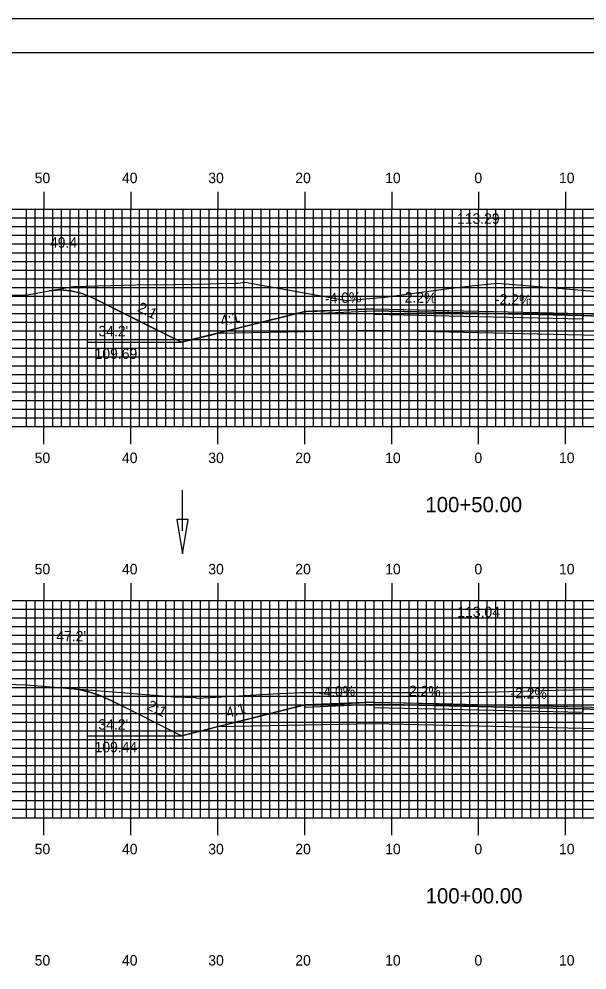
# Model space of a CAD drawing. Extents: x 1766513 to 1766856, y 442591 to 442811.
# Drawn here: x 1766626 to 1766691.4, y 442701.2 to 442810.5 of the extents above; entities that cross this region are included whole.
import ezdxf

# ---------------------------------------------------------------- set-up
doc = ezdxf.new("R2010")
doc.units = 0
for name, color, linetype in [('ANNOTATION', 7, 'Continuous'), ('BORDER', 7, 'Continuous'), ('D_Drainage_Ditch_Line', 7, 'Continuous'), ('D_Roadway_Centerline', 7, 'Continuous'), ('D_Roadway_Centerline_Text', 7, 'Continuous'), ('D_Roadway_Edge_Shoulder', 7, 'Continuous'), ('D_Roadway_Edge_TW', 7, 'Continuous'), ('D_Roadway_Pavement', 7, 'Continuous'), ('D_Roadway_SlopeLines', 7, 'Continuous'), ('D_Roadway_SubGrade', 7, 'Continuous'), ('D_Text_Standard', 7, 'Continuous'), ('H_V ANNOTATION', 7, 'Continuous'), ('MAJOR', 7, 'Continuous'), ('MINOR', 7, 'Continuous'), ('PDRAIN', 7, 'Continuous'), ('PLOT BOUNDARY', 7, 'Continuous'), ('S_Roadway_Centerline', 7, 'Continuous')]:
    doc.layers.add(name, color=color, linetype=linetype)

msp = doc.modelspace()

# ---------------------------------------------------------------- linework, layer by layer
at = {"layer": 'BORDER'}
msp.add_lwpolyline([(1766529.31, 442596.67), (1766849.31, 442596.67), (1766849.31, 442806.67), (1766529.31, 442806.67)], close=True, dxfattribs=at)
at = {"layer": 'D_Drainage_Ditch_Line'}
msp.add_line((1766644.85, 442751.66), (1766644.85, 442756.36), dxfattribs=at)
msp.add_lwpolyline([(1766645.5, 442752.97), (1766644.19, 442752.97), (1766644.85, 442749.03)], close=True, dxfattribs=at)
at = {"layer": 'D_Roadway_Centerline'}
for points in [[(1766629.51, 442779.27), (1766630.76, 442779.39), (1766631.63, 442779.32), (1766632.01, 442779.29), (1766633.03, 442779.04), (1766633.26, 442778.99), (1766634.51, 442778.47), (1766638.94, 442776.25), (1766644.74, 442773.36), (1766648.51, 442774.3), (1766648.74, 442774.36), (1766658.91, 442776.9), (1766660.34, 442776.96), (1766666.91, 442777.22), (1766675.35, 442777.03), (1766678.91, 442776.96), (1766690.91, 442776.69), (1766698.91, 442776.37)], [(1766631.7, 442733.58), (1766632.95, 442733.41), (1766634.2, 442733.11), (1766635.45, 442732.69), (1766636.7, 442732.13), (1766639.51, 442730.72), (1766644.74, 442728.11), (1766648.06, 442728.94), (1766648.74, 442729.11), (1766650.05, 442729.44), (1766658.91, 442731.65), (1766658.91, 442731.65), (1766663.43, 442731.83), (1766666.91, 442731.97), (1766674.35, 442731.81), (1766678.91, 442731.71), (1766690.91, 442731.44), (1766697.03, 442731.2)]]:
    msp.add_lwpolyline(points, dxfattribs=at)
at = {"layer": 'D_Roadway_Edge_Shoulder'}
for points in [[(1766666.91, 442777.22), (1766658.91, 442776.9), (1766658.91, 442776.65), (1766666.91, 442776.97)], [(1766690.91, 442776.69), (1766698.91, 442776.37), (1766698.91, 442776.12), (1766690.91, 442776.44)], [(1766666.91, 442731.97), (1766658.91, 442731.65), (1766658.91, 442731.4), (1766666.91, 442731.72)], [(1766690.91, 442731.44), (1766698.91, 442731.12), (1766698.91, 442730.87), (1766690.91, 442731.19)]]:
    msp.add_lwpolyline(points, close=True, dxfattribs=at)
at = {"layer": 'D_Roadway_Edge_TW'}
for points in [[(1766666.91, 442776.97), (1766666.91, 442777.22), (1766678.91, 442776.96), (1766690.91, 442776.69), (1766690.91, 442776.44), (1766678.91, 442776.71)], [(1766666.91, 442731.72), (1766666.91, 442731.97), (1766678.91, 442731.71), (1766690.91, 442731.44), (1766690.91, 442731.19), (1766678.91, 442731.46)]]:
    msp.add_lwpolyline(points, close=True, dxfattribs=at)
at = {"layer": 'D_Roadway_Pavement'}
for points in [[(1766666.91, 442776.55), (1766666.91, 442776.97), (1766678.91, 442776.71), (1766690.91, 442776.44), (1766690.91, 442776.03), (1766678.91, 442776.29)], [(1766666.91, 442731.3), (1766666.91, 442731.72), (1766678.91, 442731.46), (1766690.91, 442731.19), (1766690.91, 442730.78), (1766678.91, 442731.04)]]:
    msp.add_lwpolyline(points, close=True, dxfattribs=at)
at = {"layer": 'D_Roadway_SlopeLines'}
for points in [[(1766644.74, 442773.36), (1766634.51, 442778.47), (1766633.26, 442778.99), (1766632.01, 442779.29), (1766630.76, 442779.39), (1766629.51, 442779.27)], [(1766658.91, 442776.9), (1766644.74, 442773.36)], [(1766644.74, 442728.11), (1766636.7, 442732.13), (1766635.45, 442732.69), (1766634.2, 442733.11), (1766632.95, 442733.41), (1766631.7, 442733.58)], [(1766658.91, 442731.65), (1766644.74, 442728.11)]]:
    msp.add_lwpolyline(points, dxfattribs=at)
at = {"layer": 'D_Roadway_SubGrade'}
for points in [[(1766666.91, 442774.72), (1766648.74, 442774.36), (1766658.91, 442776.9), (1766658.91, 442776.65), (1766666.91, 442776.97), (1766678.91, 442776.71), (1766690.91, 442776.44), (1766698.91, 442776.12), (1766698.91, 442776.37), (1766709.08, 442773.83), (1766690.91, 442774.19), (1766678.91, 442774.46)], [(1766666.91, 442729.47), (1766648.74, 442729.11), (1766658.91, 442731.65), (1766658.91, 442731.4), (1766666.91, 442731.72), (1766678.91, 442731.46), (1766690.91, 442731.19), (1766698.91, 442730.87), (1766698.91, 442731.12), (1766709.08, 442728.58), (1766690.91, 442728.94), (1766678.91, 442729.21)]]:
    msp.add_lwpolyline(points, close=True, dxfattribs=at)
at = {"layer": 'MAJOR'}
for p, q in [((1766628.91, 442790.67), (1766628.91, 442788.67)), ((1766638.91, 442790.67), (1766638.91, 442788.67)), ((1766648.91, 442790.67), (1766648.91, 442788.67)), ((1766658.91, 442790.67), (1766658.91, 442788.67)), ((1766668.91, 442790.67), (1766668.91, 442788.67)), ((1766678.91, 442790.67), (1766678.91, 442788.67)), ((1766688.91, 442790.67), (1766688.91, 442788.67)), ((1766538.91, 442788.67), (1766818.91, 442788.67)), ((1766538.91, 442788.67), (1766818.91, 442788.67)), ((1766628.91, 442763.67), (1766628.91, 442788.67)), ((1766638.91, 442763.67), (1766638.91, 442788.67)), ((1766648.91, 442763.67), (1766648.91, 442788.67)), ((1766658.91, 442763.67), (1766658.91, 442788.67)), ((1766668.91, 442763.67), (1766668.91, 442788.67)), ((1766678.91, 442763.67), (1766678.91, 442788.67)), ((1766688.91, 442763.67), (1766688.91, 442788.67)), ((1766538.91, 442783.67), (1766818.91, 442783.67)), ((1766538.91, 442778.67), (1766818.91, 442778.67)), ((1766538.91, 442773.67), (1766818.91, 442773.67)), ((1766538.91, 442768.67), (1766818.91, 442768.67)), ((1766538.91, 442763.67), (1766818.91, 442763.67)), ((1766538.91, 442763.67), (1766818.91, 442763.67)), ((1766628.91, 442761.66), (1766628.91, 442763.67)), ((1766638.91, 442761.66), (1766638.91, 442763.67)), ((1766648.91, 442761.66), (1766648.91, 442763.67)), ((1766658.91, 442761.66), (1766658.91, 442763.67)), ((1766668.91, 442761.66), (1766668.91, 442763.67)), ((1766678.91, 442761.66), (1766678.91, 442763.67)), ((1766688.91, 442761.66), (1766688.91, 442763.67)), ((1766628.91, 442745.67), (1766628.91, 442743.67)), ((1766638.91, 442745.67), (1766638.91, 442743.67)), ((1766648.91, 442745.67), (1766648.91, 442743.67)), ((1766658.91, 442745.67), (1766658.91, 442743.67)), ((1766668.91, 442745.67), (1766668.91, 442743.67)), ((1766678.91, 442745.67), (1766678.91, 442743.67)), ((1766688.91, 442745.67), (1766688.91, 442743.67)), ((1766538.91, 442743.67), (1766818.91, 442743.67)), ((1766538.91, 442743.67), (1766818.91, 442743.67)), ((1766628.91, 442718.67), (1766628.91, 442743.67)), ((1766638.91, 442718.67), (1766638.91, 442743.67)), ((1766648.91, 442718.67), (1766648.91, 442743.67)), ((1766658.91, 442718.67), (1766658.91, 442743.67)), ((1766668.91, 442718.67), (1766668.91, 442743.67)), ((1766678.91, 442718.67), (1766678.91, 442743.67)), ((1766688.91, 442718.67), (1766688.91, 442743.67)), ((1766538.91, 442738.67), (1766818.91, 442738.67)), ((1766538.91, 442733.67), (1766818.91, 442733.67)), ((1766538.91, 442728.67), (1766818.91, 442728.67)), ((1766538.91, 442723.67), (1766818.91, 442723.67)), ((1766538.91, 442718.67), (1766818.91, 442718.67)), ((1766538.91, 442718.67), (1766818.91, 442718.67)), ((1766628.91, 442716.66), (1766628.91, 442718.67)), ((1766638.91, 442716.66), (1766638.91, 442718.67)), ((1766648.91, 442716.66), (1766648.91, 442718.67)), ((1766658.91, 442716.66), (1766658.91, 442718.67)), ((1766668.91, 442716.66), (1766668.91, 442718.67)), ((1766678.91, 442716.66), (1766678.91, 442718.67)), ((1766688.91, 442716.66), (1766688.91, 442718.67))]:
    msp.add_line(p, q, dxfattribs=at)
at = {"layer": 'MINOR'}
for p, q in [((1766626.91, 442763.67), (1766626.91, 442788.67)), ((1766627.91, 442763.67), (1766627.91, 442788.67)), ((1766629.91, 442763.67), (1766629.91, 442788.67)), ((1766630.91, 442763.67), (1766630.91, 442788.67)), ((1766631.91, 442763.67), (1766631.91, 442788.67)), ((1766632.91, 442763.67), (1766632.91, 442788.67)), ((1766633.91, 442763.67), (1766633.91, 442788.67)), ((1766634.91, 442763.67), (1766634.91, 442788.67)), ((1766635.91, 442763.67), (1766635.91, 442788.67)), ((1766636.91, 442763.67), (1766636.91, 442788.67)), ((1766637.91, 442763.67), (1766637.91, 442788.67)), ((1766639.91, 442763.67), (1766639.91, 442788.67)), ((1766640.91, 442763.67), (1766640.91, 442788.67)), ((1766641.91, 442763.67), (1766641.91, 442788.67)), ((1766642.91, 442763.67), (1766642.91, 442788.67)), ((1766643.91, 442763.67), (1766643.91, 442788.67)), ((1766644.91, 442763.67), (1766644.91, 442788.67)), ((1766645.91, 442763.67), (1766645.91, 442788.67)), ((1766646.91, 442763.67), (1766646.91, 442788.67)), ((1766647.91, 442763.67), (1766647.91, 442788.67)), ((1766649.91, 442763.67), (1766649.91, 442788.67)), ((1766650.91, 442763.67), (1766650.91, 442788.67)), ((1766651.91, 442763.67), (1766651.91, 442788.67)), ((1766652.91, 442763.67), (1766652.91, 442788.67)), ((1766653.91, 442763.67), (1766653.91, 442788.67)), ((1766654.91, 442763.67), (1766654.91, 442788.67)), ((1766655.91, 442763.67), (1766655.91, 442788.67)), ((1766656.91, 442763.67), (1766656.91, 442788.67)), ((1766657.91, 442763.67), (1766657.91, 442788.67)), ((1766659.91, 442763.67), (1766659.91, 442788.67)), ((1766660.91, 442763.67), (1766660.91, 442788.67)), ((1766661.91, 442763.67), (1766661.91, 442788.67)), ((1766662.91, 442763.67), (1766662.91, 442788.67)), ((1766663.91, 442763.67), (1766663.91, 442788.67)), ((1766664.91, 442763.67), (1766664.91, 442788.67)), ((1766665.91, 442763.67), (1766665.91, 442788.67)), ((1766666.91, 442763.67), (1766666.91, 442788.67)), ((1766667.91, 442763.67), (1766667.91, 442788.67)), ((1766669.91, 442763.67), (1766669.91, 442788.67)), ((1766670.91, 442763.67), (1766670.91, 442788.67)), ((1766671.91, 442763.67), (1766671.91, 442788.67)), ((1766672.91, 442763.67), (1766672.91, 442788.67)), ((1766673.91, 442763.67), (1766673.91, 442788.67)), ((1766674.91, 442763.67), (1766674.91, 442788.67)), ((1766675.91, 442763.67), (1766675.91, 442788.67)), ((1766676.91, 442763.67), (1766676.91, 442788.67)), ((1766677.91, 442763.67), (1766677.91, 442788.67)), ((1766679.91, 442763.67), (1766679.91, 442788.67)), ((1766680.91, 442763.67), (1766680.91, 442788.67)), ((1766681.91, 442763.67), (1766681.91, 442788.67)), ((1766682.91, 442763.67), (1766682.91, 442788.67)), ((1766683.91, 442763.67), (1766683.91, 442788.67)), ((1766684.91, 442763.67), (1766684.91, 442788.67)), ((1766685.91, 442763.67), (1766685.91, 442788.67)), ((1766686.91, 442763.67), (1766686.91, 442788.67)), ((1766687.91, 442763.67), (1766687.91, 442788.67)), ((1766689.91, 442763.67), (1766689.91, 442788.67)), ((1766690.91, 442763.67), (1766690.91, 442788.67)), ((1766538.91, 442787.67), (1766818.91, 442787.67)), ((1766538.91, 442786.67), (1766818.91, 442786.67)), ((1766538.91, 442785.67), (1766818.91, 442785.67)), ((1766538.91, 442784.67), (1766818.91, 442784.67)), ((1766538.91, 442782.67), (1766818.91, 442782.67)), ((1766538.91, 442781.67), (1766818.91, 442781.67)), ((1766538.91, 442780.67), (1766818.91, 442780.67)), ((1766538.91, 442779.67), (1766818.91, 442779.67)), ((1766538.91, 442777.67), (1766818.91, 442777.67)), ((1766538.91, 442776.67), (1766818.91, 442776.67)), ((1766538.91, 442775.67), (1766818.91, 442775.67)), ((1766538.91, 442774.67), (1766818.91, 442774.67)), ((1766538.91, 442772.67), (1766818.91, 442772.67)), ((1766538.91, 442771.67), (1766818.91, 442771.67)), ((1766538.91, 442770.67), (1766818.91, 442770.67)), ((1766538.91, 442769.67), (1766818.91, 442769.67)), ((1766538.91, 442767.67), (1766818.91, 442767.67)), ((1766538.91, 442766.67), (1766818.91, 442766.67)), ((1766538.91, 442765.67), (1766818.91, 442765.67)), ((1766538.91, 442764.67), (1766818.91, 442764.67)), ((1766626.91, 442718.67), (1766626.91, 442743.67)), ((1766627.91, 442718.67), (1766627.91, 442743.67)), ((1766629.91, 442718.67), (1766629.91, 442743.67)), ((1766630.91, 442718.67), (1766630.91, 442743.67)), ((1766631.91, 442718.67), (1766631.91, 442743.67)), ((1766632.91, 442718.67), (1766632.91, 442743.67)), ((1766633.91, 442718.67), (1766633.91, 442743.67)), ((1766634.91, 442718.67), (1766634.91, 442743.67)), ((1766635.91, 442718.67), (1766635.91, 442743.67)), ((1766636.91, 442718.67), (1766636.91, 442743.67)), ((1766637.91, 442718.67), (1766637.91, 442743.67)), ((1766639.91, 442718.67), (1766639.91, 442743.67)), ((1766640.91, 442718.67), (1766640.91, 442743.67)), ((1766641.91, 442718.67), (1766641.91, 442743.67)), ((1766642.91, 442718.67), (1766642.91, 442743.67)), ((1766643.91, 442718.67), (1766643.91, 442743.67)), ((1766644.91, 442718.67), (1766644.91, 442743.67)), ((1766645.91, 442718.67), (1766645.91, 442743.67)), ((1766646.91, 442718.67), (1766646.91, 442743.67)), ((1766647.91, 442718.67), (1766647.91, 442743.67)), ((1766649.91, 442718.67), (1766649.91, 442743.67)), ((1766650.91, 442718.67), (1766650.91, 442743.67)), ((1766651.91, 442718.67), (1766651.91, 442743.67)), ((1766652.91, 442718.67), (1766652.91, 442743.67)), ((1766653.91, 442718.67), (1766653.91, 442743.67)), ((1766654.91, 442718.67), (1766654.91, 442743.67)), ((1766655.91, 442718.67), (1766655.91, 442743.67)), ((1766656.91, 442718.67), (1766656.91, 442743.67)), ((1766657.91, 442718.67), (1766657.91, 442743.67)), ((1766659.91, 442718.67), (1766659.91, 442743.67)), ((1766660.91, 442718.67), (1766660.91, 442743.67)), ((1766661.91, 442718.67), (1766661.91, 442743.67)), ((1766662.91, 442718.67), (1766662.91, 442743.67)), ((1766663.91, 442718.67), (1766663.91, 442743.67)), ((1766664.91, 442718.67), (1766664.91, 442743.67)), ((1766665.91, 442718.67), (1766665.91, 442743.67)), ((1766666.91, 442718.67), (1766666.91, 442743.67)), ((1766667.91, 442718.67), (1766667.91, 442743.67)), ((1766669.91, 442718.67), (1766669.91, 442743.67)), ((1766670.91, 442718.67), (1766670.91, 442743.67)), ((1766671.91, 442718.67), (1766671.91, 442743.67)), ((1766672.91, 442718.67), (1766672.91, 442743.67)), ((1766673.91, 442718.67), (1766673.91, 442743.67)), ((1766674.91, 442718.67), (1766674.91, 442743.67)), ((1766675.91, 442718.67), (1766675.91, 442743.67)), ((1766676.91, 442718.67), (1766676.91, 442743.67)), ((1766677.91, 442718.67), (1766677.91, 442743.67)), ((1766679.91, 442718.67), (1766679.91, 442743.67)), ((1766680.91, 442718.67), (1766680.91, 442743.67)), ((1766681.91, 442718.67), (1766681.91, 442743.67)), ((1766682.91, 442718.67), (1766682.91, 442743.67)), ((1766683.91, 442718.67), (1766683.91, 442743.67)), ((1766684.91, 442718.67), (1766684.91, 442743.67)), ((1766685.91, 442718.67), (1766685.91, 442743.67)), ((1766686.91, 442718.67), (1766686.91, 442743.67)), ((1766687.91, 442718.67), (1766687.91, 442743.67)), ((1766689.91, 442718.67), (1766689.91, 442743.67)), ((1766690.91, 442718.67), (1766690.91, 442743.67)), ((1766538.91, 442742.67), (1766818.91, 442742.67)), ((1766538.91, 442741.67), (1766818.91, 442741.67)), ((1766538.91, 442740.67), (1766818.91, 442740.67)), ((1766538.91, 442739.67), (1766818.91, 442739.67)), ((1766538.91, 442737.67), (1766818.91, 442737.67)), ((1766538.91, 442736.67), (1766818.91, 442736.67)), ((1766538.91, 442735.67), (1766818.91, 442735.67)), ((1766538.91, 442734.67), (1766818.91, 442734.67)), ((1766538.91, 442732.67), (1766818.91, 442732.67)), ((1766538.91, 442731.67), (1766818.91, 442731.67)), ((1766538.91, 442730.67), (1766818.91, 442730.67)), ((1766538.91, 442729.67), (1766818.91, 442729.67)), ((1766538.91, 442727.67), (1766818.91, 442727.67)), ((1766538.91, 442726.67), (1766818.91, 442726.67)), ((1766538.91, 442725.67), (1766818.91, 442725.67)), ((1766538.91, 442724.67), (1766818.91, 442724.67)), ((1766538.91, 442722.67), (1766818.91, 442722.67)), ((1766538.91, 442721.67), (1766818.91, 442721.67)), ((1766538.91, 442720.67), (1766818.91, 442720.67)), ((1766538.91, 442719.67), (1766818.91, 442719.67))]:
    msp.add_line(p, q, dxfattribs=at)
at = {"layer": 'PDRAIN'}
for p, q in [((1766634.01, 442773.36), (1766644.74, 442773.36)), ((1766634.01, 442728.11), (1766644.74, 442728.11))]:
    msp.add_line(p, q, dxfattribs=at)
at = {"layer": 'PLOT BOUNDARY'}
msp.add_lwpolyline([(1766513.12, 442590.55), (1766853.12, 442590.55), (1766853.12, 442810.55), (1766513.12, 442810.55)], close=True, dxfattribs=at)
at = {"layer": 'S_Roadway_Centerline'}
for points in [[(1766624.73, 442778.8), (1766626.23, 442778.81), (1766626.78, 442778.79), (1766632.27, 442779.76), (1766640.92, 442779.99), (1766641.66, 442779.96), (1766648.07, 442780.08), (1766649.09, 442780.11), (1766650.89, 442780.16), (1766651.15, 442780.15), (1766651.23, 442780.15), (1766652.03, 442780.27), (1766663.75, 442778.16), (1766668.13, 442778.55), (1766674.3, 442779.41), (1766677.38, 442779.78), (1766681.1, 442780.16), (1766693.09, 442779.16), (1766702.46, 442780.05), (1766713.25, 442780.62), (1766720.31, 442781.41), (1766736.42, 442780.44), (1766746.09, 442780.38)], [(1766616.64, 442734.31), (1766626.82, 442733.97), (1766643.96, 442732.59), (1766646.35, 442732.5), (1766646.57, 442732.41), (1766649.33, 442732.56), (1766655.29, 442732.91), (1766658.44, 442733.09), (1766661.35, 442733.08), (1766672.82, 442733.06), (1766675.13, 442733.03), (1766679.72, 442733.11), (1766687.81, 442733.33), (1766691.7, 442733.42), (1766706.32, 442733.12), (1766710.37, 442733.06), (1766711.41, 442732.95), (1766711.68, 442732.95), (1766713.44, 442732.89), (1766729.11, 442732.56), (1766735.39, 442732.32), (1766736.6, 442732.25), (1766739.94, 442732.05), (1766742.27, 442731.91)]]:
    msp.add_lwpolyline(points, dxfattribs=at)

# ---------------------------------------------------------------- texts
at = {"layer": 'ANNOTATION'}
for s, rotation, p in [('-4.0%', 2.2906, (1766661.26, 442777.8)), ('2.2%', 358.7397, (1766670.39, 442777.94)), ('-2.2%', 358.7397, (1766680.78, 442777.72)), ('2:1', 333.4359, (1766639.56, 442776.98)), ('4:1', 14.0398, (1766649.37, 442775.21)), ('-4.0%', 2.2906, (1766660.54, 442732.52)), ('2.2%', 358.7397, (1766670.88, 442732.68)), ('-2.2%', 358.7397, (1766682.56, 442732.43)), ('2:1', 333.4347, (1766640.65, 442731.19)), ('4:1', 14.0386, (1766650.03, 442730.16))]:
    msp.add_text(s, height=1.2, rotation=rotation, dxfattribs=at).set_placement(p)
for s, p in [("34.2'", (1766635.17, 442774.05)), ('109.69', (1766634.73, 442771.45)), ("34.2'", (1766635.17, 442728.8)), ('109.44', (1766634.73, 442726.2))]:
    msp.add_text(s, height=1.2, dxfattribs=at).set_placement(p)
at = {"layer": 'D_Roadway_Centerline'}
for s, p in [('C', (1766678.9, 442776.96)), ('L', (1766678.91, 442776.95)), ('C', (1766678.91, 442731.71)), ('L', (1766678.91, 442731.7))]:
    msp.add_text(s, height=0.0146, dxfattribs=at).set_placement(p)
at = {"layer": 'D_Roadway_Centerline_Text'}
for s, p in [('113.29', (1766676.42, 442786.99)), ('113.04', (1766676.46, 442741.74))]:
    msp.add_text(s, height=1.2, dxfattribs=at).set_placement(p)
at = {"layer": 'D_Text_Standard'}
for s, p in [("49.4'", (1766629.6, 442784.24)), ("47.2'", (1766630.32, 442738.96))]:
    msp.add_text(s, height=1.2, dxfattribs=at).set_placement(p)
at = {"layer": 'H_V ANNOTATION'}
for s, height, p in [('50', 1.2, (1766627.84, 442791.67)), ('40', 1.2, (1766637.88, 442791.67)), ('30', 1.2, (1766647.81, 442791.67)), ('20', 1.2, (1766657.82, 442791.67)), ('10', 1.2, (1766668.16, 442791.67)), ('0', 1.2, (1766678.43, 442791.67)), ('10', 1.2, (1766688.16, 442791.67)), ('50', 1.2, (1766627.84, 442759.47)), ('40', 1.2, (1766637.88, 442759.47)), ('30', 1.2, (1766647.81, 442759.47)), ('20', 1.2, (1766657.82, 442759.47)), ('10', 1.2, (1766668.16, 442759.47)), ('0', 1.2, (1766678.43, 442759.47)), ('10', 1.2, (1766688.16, 442759.47)), ('100+50.00', 1.75, (1766672.79, 442753.82)), ('50', 1.2, (1766627.84, 442746.67)), ('40', 1.2, (1766637.88, 442746.67)), ('30', 1.2, (1766647.81, 442746.67)), ('20', 1.2, (1766657.82, 442746.67)), ('10', 1.2, (1766668.16, 442746.67)), ('0', 1.2, (1766678.43, 442746.67)), ('10', 1.2, (1766688.16, 442746.67)), ('50', 1.2, (1766627.84, 442714.47)), ('40', 1.2, (1766637.88, 442714.47)), ('30', 1.2, (1766647.81, 442714.47)), ('20', 1.2, (1766657.82, 442714.47)), ('10', 1.2, (1766668.16, 442714.47)), ('0', 1.2, (1766678.43, 442714.47)), ('10', 1.2, (1766688.16, 442714.47)), ('100+00.00', 1.75, (1766672.82, 442708.82)), ('50', 1.2, (1766627.84, 442701.67)), ('40', 1.2, (1766637.88, 442701.67)), ('30', 1.2, (1766647.81, 442701.67)), ('20', 1.2, (1766657.82, 442701.67)), ('10', 1.2, (1766668.16, 442701.67)), ('0', 1.2, (1766678.43, 442701.67)), ('10', 1.2, (1766688.16, 442701.67))]:
    msp.add_text(s, height=height, dxfattribs=at).set_placement(p)

doc.saveas('drawing.dxf')
